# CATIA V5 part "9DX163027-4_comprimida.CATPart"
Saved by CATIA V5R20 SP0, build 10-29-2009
Part number: 9DX163027-4_comprimida
Revision: ANY
Definition: UNKNOWN
Nomenclature: 9DX163027-4_comprimida
Source: Unknown
Bounding box of the stored display mesh (mm): x -12.8 to 12.8, y -0.8 to 6.8, z -12.8 to 12.8
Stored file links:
  C:\Users\Utente\Desktop\IO LAVORO\3D X SITO CF\CUMSA\3D files DX\DX 163027\9DX163027-4_comprimida.CATPart
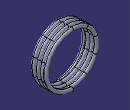
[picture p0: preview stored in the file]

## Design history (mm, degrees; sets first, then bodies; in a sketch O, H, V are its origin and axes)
Body1 "Revolución2" (main body)
  Solid1: solid without history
